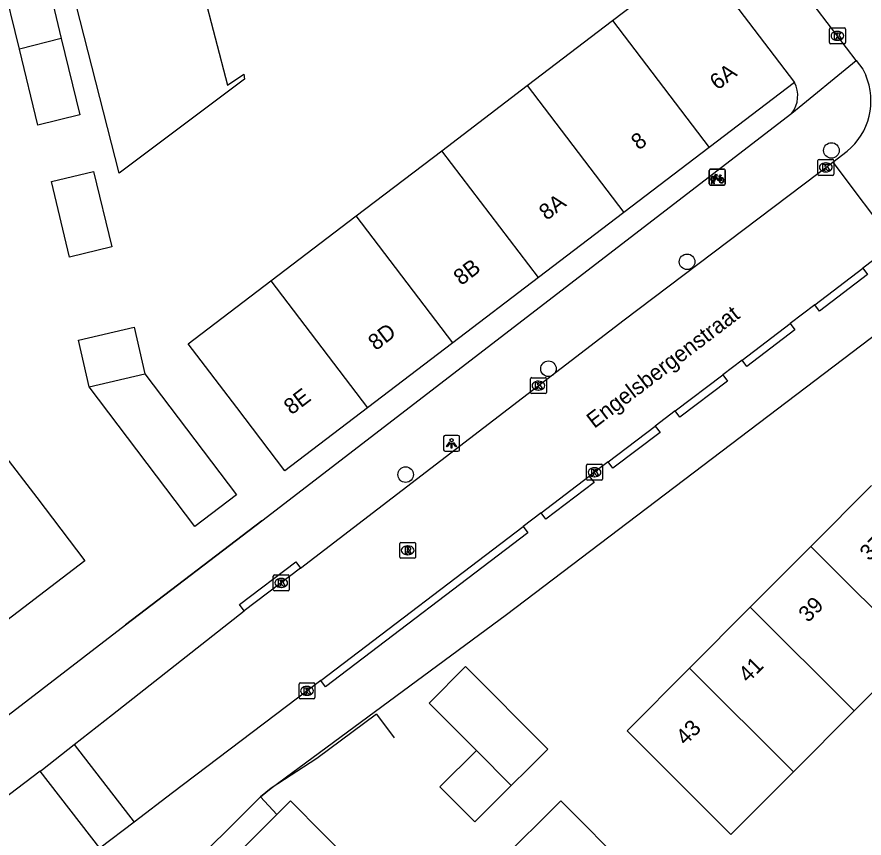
# Model space of a CAD drawing. Extents: x 159961 to 160856, y 382704 to 383353.
# Drawn here: x 160039 to 160092.3, y 383159 to 383210.6 of the extents above; entities that cross this region are included whole.
import ezdxf

# ---------------------------------------------------------------- set-up
doc = ezdxf.new("R2010")
doc.units = 0
for name, color, linetype in [('IMGEO_Boom', 7, 'Continuous'), ('IMGEO_Fietsenrek', 7, 'Continuous'), ('IMGEO_Kolk', 7, 'Continuous'), ('IMGEO_Lichtpunt', 7, 'Continuous'), ('IMGEO_Muur', 7, 'Continuous'), ('IMGEO_Openbare_ruimte_label', 7, 'Continuous'), ('IMGEO_Pand', 7, 'Continuous'), ('IMGEO_Pand_nummerreeks', 7, 'Continuous'), ('IMGEO_Rijbaan_lokaal_open', 7, 'Continuous'), ('IMGEO_Rioolput', 7, 'Continuous'), ('IMGEO_Voetpad_open', 7, 'Continuous')]:
    doc.layers.add(name, color=color, linetype=linetype)

msp = doc.modelspace()

# ---------------------------------------------------------------- linework, layer by layer
at = {"layer": 'IMGEO_Boom'}
for centre in [(160090.197, 383202.176), (160081.127, 383195.18), (160072.413, 383188.462), (160063.433, 383181.809)]:
    msp.add_circle(centre, 0.489, dxfattribs=at)
at = {"layer": 'IMGEO_Fietsenrek'}
for p, q in [((160082.523, 383200.074), (160082.523, 383200.915)), ((160082.523, 383200.915), (160082.523, 383200.074)), ((160082.598, 383200.999), (160083.439, 383200.999)), ((160083.439, 383200.999), (160082.598, 383200.999)), ((160083.523, 383200.924), (160083.523, 383200.083)), ((160083.523, 383200.083), (160083.523, 383200.924)), ((160082.65, 383200.083), (160082.689, 383200.243)), ((160082.719, 383200.231), (160082.684, 383200.083)), ((160082.761, 383200.255), (160082.76, 383200.259)), ((160082.802, 383200.083), (160082.768, 383200.225)), ((160082.792, 383200.266), (160082.793, 383200.259)), ((160082.8, 383200.229), (160082.835, 383200.083)), ((160083.21, 383200.548), (160083.246, 383200.453)), ((160083.448, 383199.999), (160082.607, 383199.999)), ((160082.607, 383199.999), (160083.448, 383199.999)), ((160082.684, 383200.083), (160082.65, 383200.083)), ((160082.835, 383200.083), (160082.802, 383200.083))]:
    msp.add_line(p, q, dxfattribs=at)
for points in [[(160082.836, 383200.525), (160082.931, 383200.689), (160083.017, 383200.675), (160083.019, 383200.666), (160082.963, 383200.655), (160082.936, 383200.61), (160083.192, 383200.569)], [(160082.857, 383200.473), (160082.805, 383200.383), (160082.765, 383200.358), (160082.766, 383200.405), (160082.821, 383200.499)], [(160083.132, 383200.281), (160083.082, 383200.281), (160082.891, 383200.532), (160082.872, 383200.5)], [(160083.179, 383200.544), (160082.922, 383200.585), (160082.905, 383200.556), (160083.072, 383200.336), (160083.179, 383200.544)], [(160083.227, 383200.446), (160083.197, 383200.523), (160083.088, 383200.305), (160083.131, 383200.305)], [(160083.161, 383200.305), (160083.281, 383200.304), (160083.237, 383200.418)], [(160083.257, 383200.425), (160083.312, 383200.28), (160083.162, 383200.28)], [(160083.192, 383200.569), (160083.217, 383200.618), (160083.211, 383200.622), (160083.188, 383200.626), (160083.176, 383200.633), (160083.175, 383200.636), (160083.177, 383200.641), (160083.272, 383200.626), (160083.274, 383200.616), (160083.264, 383200.603), (160083.252, 383200.597), (160083.238, 383200.603), (160083.21, 383200.548)]]:
    msp.add_lwpolyline(points, dxfattribs=at)
for centre, radius, start, end in [((160082.601, 383200.921), 0.0779, 92.4484, 184.2845), ((160082.601, 383200.921), 0.0779, 92.4484, 184.2845), ((160083.445, 383200.921), 0.0779, 2.4484, 94.2845), ((160083.445, 383200.921), 0.0779, 2.4484, 94.2845), ((160082.763, 383200.384), 0.159, 62.6766, 242.1369), ((160082.763, 383200.384), 0.129, 63.3192, 238.903), ((160082.743, 383200.255), 0.0499, 12.8025, 158.6934), ((160082.763, 383200.384), 0.159, 253.9967, 271.7867), ((160082.743, 383200.255), 0.0174, 12.8025, 163.4502), ((160082.763, 383200.384), 0.129, 253.415, 269.0204), ((160082.763, 383200.384), 0.129, 283.6043, 43.4302), ((160082.763, 383200.384), 0.159, 283.5766, 46.6042), ((160083.29, 383200.3), 0.159, 113.3408, 178.3217), ((160083.29, 383200.3), 0.159, 187.0065, 105.7708), ((160083.29, 383200.3), 0.129, 113.923, 177.9556), ((160083.29, 383200.3), 0.129, 188.6715, 104.5883), ((160082.601, 383200.077), 0.0779, 182.4484, 274.2845), ((160082.601, 383200.077), 0.0779, 182.4484, 274.2845), ((160083.445, 383200.077), 0.0779, 272.4484, 4.2845), ((160083.445, 383200.077), 0.0779, 272.4484, 4.2845)]:
    msp.add_arc(centre, radius, start, end, dxfattribs=at)
at = {"layer": 'IMGEO_Kolk'}
for p, q in [((160090.077, 383208.951), (160090.077, 383209.803)), ((160090.152, 383209.877), (160091.004, 383209.877)), ((160091.078, 383209.803), (160091.078, 383208.951)), ((160090.565, 383209.657), (160090.59, 383209.657)), ((160091.004, 383208.877), (160090.152, 383208.877)), ((160090.588, 383209.097), (160090.563, 383209.097)), ((160089.346, 383200.687), (160089.346, 383201.539)), ((160089.421, 383201.613), (160090.273, 383201.613)), ((160089.834, 383201.393), (160089.859, 383201.393)), ((160090.347, 383201.539), (160090.347, 383200.687)), ((160089.857, 383200.833), (160089.832, 383200.833)), ((160090.273, 383200.613), (160089.421, 383200.613)), ((160071.358, 383187.9), (160072.21, 383187.9)), ((160071.283, 383186.974), (160071.283, 383187.826)), ((160071.771, 383187.68), (160071.796, 383187.68)), ((160072.284, 383187.826), (160072.284, 383186.974)), ((160072.21, 383186.9), (160071.358, 383186.9)), ((160071.794, 383187.12), (160071.769, 383187.12)), ((160074.808, 383181.531), (160074.808, 383182.383)), ((160074.883, 383182.457), (160075.735, 383182.457)), ((160075.296, 383182.237), (160075.321, 383182.237)), ((160075.809, 383182.383), (160075.809, 383181.531)), ((160075.319, 383181.677), (160075.294, 383181.677)), ((160075.735, 383181.457), (160074.883, 383181.457)), ((160055.114, 383174.579), (160055.114, 383175.431)), ((160055.189, 383175.505), (160056.041, 383175.505)), ((160055.602, 383175.285), (160055.627, 383175.285)), ((160056.115, 383175.431), (160056.115, 383174.579)), ((160055.625, 383174.725), (160055.6, 383174.725)), ((160056.041, 383174.505), (160055.189, 383174.505)), ((160056.808, 383168.721), (160057.66, 383168.721)), ((160056.733, 383167.795), (160056.733, 383168.647)), ((160057.221, 383168.501), (160057.246, 383168.501)), ((160057.734, 383168.647), (160057.734, 383167.795)), ((160057.66, 383167.721), (160056.808, 383167.721)), ((160057.244, 383167.941), (160057.219, 383167.941))]:
    msp.add_line(p, q, dxfattribs=at)
for points in [[(160090.077, 383208.951), (160090.077, 383209.803)], [(160090.152, 383209.877), (160091.004, 383209.877)], [(160091.078, 383209.803), (160091.078, 383208.951)], [(160090.398, 383209.577), (160090.521, 383209.577), (160090.521, 383209.426), (160090.651, 383209.577), (160090.815, 383209.577), (160090.669, 383209.426), (160090.822, 383209.177), (160090.67, 383209.177), (160090.585, 383209.341), (160090.521, 383209.274), (160090.521, 383209.177), (160090.398, 383209.177), (160090.398, 383209.577)], [(160091.004, 383208.877), (160090.152, 383208.877)], [(160089.346, 383200.687), (160089.346, 383201.539)], [(160089.421, 383201.613), (160090.273, 383201.613)], [(160089.667, 383201.313), (160089.79, 383201.313), (160089.79, 383201.162), (160089.92, 383201.313), (160090.084, 383201.313), (160089.938, 383201.162), (160090.091, 383200.913), (160089.939, 383200.913), (160089.854, 383201.077), (160089.79, 383201.01), (160089.79, 383200.913), (160089.667, 383200.913), (160089.667, 383201.313)], [(160090.347, 383201.539), (160090.347, 383200.687)], [(160090.273, 383200.613), (160089.421, 383200.613)], [(160071.358, 383187.9), (160072.21, 383187.9)], [(160071.283, 383186.974), (160071.283, 383187.826)], [(160071.604, 383187.6), (160071.727, 383187.6), (160071.727, 383187.449), (160071.857, 383187.6), (160072.021, 383187.6), (160071.875, 383187.449), (160072.028, 383187.2), (160071.876, 383187.2), (160071.791, 383187.364), (160071.727, 383187.297), (160071.727, 383187.2), (160071.604, 383187.2), (160071.604, 383187.6)], [(160072.284, 383187.826), (160072.284, 383186.974)], [(160072.21, 383186.9), (160071.358, 383186.9)], [(160074.808, 383181.531), (160074.808, 383182.383)], [(160074.883, 383182.457), (160075.735, 383182.457)], [(160075.129, 383182.157), (160075.252, 383182.157), (160075.252, 383182.006), (160075.382, 383182.157), (160075.546, 383182.157), (160075.4, 383182.006), (160075.553, 383181.757), (160075.401, 383181.757), (160075.316, 383181.921), (160075.252, 383181.854), (160075.252, 383181.757), (160075.129, 383181.757), (160075.129, 383182.157)], [(160075.809, 383182.383), (160075.809, 383181.531)], [(160075.735, 383181.457), (160074.883, 383181.457)], [(160055.114, 383174.579), (160055.114, 383175.431)], [(160055.189, 383175.505), (160056.041, 383175.505)], [(160055.435, 383175.205), (160055.558, 383175.205), (160055.558, 383175.054), (160055.688, 383175.205), (160055.852, 383175.205), (160055.706, 383175.054), (160055.859, 383174.805), (160055.707, 383174.805), (160055.622, 383174.969), (160055.558, 383174.902), (160055.558, 383174.805), (160055.435, 383174.805), (160055.435, 383175.205)], [(160056.115, 383175.431), (160056.115, 383174.579)], [(160056.041, 383174.505), (160055.189, 383174.505)], [(160056.808, 383168.721), (160057.66, 383168.721)], [(160056.733, 383167.795), (160056.733, 383168.647)], [(160057.054, 383168.421), (160057.177, 383168.421), (160057.177, 383168.27), (160057.307, 383168.421), (160057.471, 383168.421), (160057.325, 383168.27), (160057.478, 383168.021), (160057.326, 383168.021), (160057.241, 383168.185), (160057.177, 383168.118), (160057.177, 383168.021), (160057.054, 383168.021), (160057.054, 383168.421)], [(160057.734, 383168.647), (160057.734, 383167.795)], [(160057.66, 383167.721), (160056.808, 383167.721)]]:
    msp.add_lwpolyline(points, dxfattribs=at)
for centre, start, end in [((160090.154, 383209.801), 91.552, 178.448), ((160090.154, 383209.801), 91.552, 178.448), ((160091.002, 383209.801), 1.552, 88.448), ((160091.002, 383209.801), 1.552, 88.448), ((160090.154, 383208.953), 181.552, 268.448), ((160090.154, 383208.953), 181.552, 268.448), ((160091.002, 383208.953), 271.552, 358.448), ((160091.002, 383208.953), 271.552, 358.448), ((160089.423, 383201.537), 91.552, 178.448), ((160089.423, 383201.537), 91.552, 178.448), ((160090.271, 383201.537), 1.552, 88.448), ((160090.271, 383201.537), 1.552, 88.448), ((160089.423, 383200.689), 181.552, 268.448), ((160089.423, 383200.689), 181.552, 268.448), ((160090.271, 383200.689), 271.552, 358.448), ((160090.271, 383200.689), 271.552, 358.448), ((160071.36, 383187.824), 91.552, 178.448), ((160071.36, 383187.824), 91.552, 178.448), ((160072.208, 383187.824), 1.552, 88.448), ((160072.208, 383187.824), 1.552, 88.448), ((160071.36, 383186.976), 181.552, 268.448), ((160071.36, 383186.976), 181.552, 268.448), ((160072.208, 383186.976), 271.552, 358.448), ((160072.208, 383186.976), 271.552, 358.448), ((160074.885, 383182.381), 91.552, 178.448), ((160074.885, 383182.381), 91.552, 178.448), ((160075.733, 383182.381), 1.552, 88.448), ((160075.733, 383182.381), 1.552, 88.448), ((160074.885, 383181.533), 181.552, 268.448), ((160074.885, 383181.533), 181.552, 268.448), ((160075.733, 383181.533), 271.552, 358.448), ((160075.733, 383181.533), 271.552, 358.448), ((160055.191, 383175.429), 91.552, 178.448), ((160055.191, 383175.429), 91.552, 178.448), ((160056.039, 383175.429), 1.552, 88.448), ((160056.039, 383175.429), 1.552, 88.448), ((160055.191, 383174.581), 181.552, 268.448), ((160055.191, 383174.581), 181.552, 268.448), ((160056.039, 383174.581), 271.552, 358.448), ((160056.039, 383174.581), 271.552, 358.448), ((160056.81, 383168.645), 91.552, 178.448), ((160056.81, 383168.645), 91.552, 178.448), ((160057.658, 383168.645), 1.552, 88.448), ((160057.658, 383168.645), 1.552, 88.448), ((160056.81, 383167.797), 181.552, 268.448), ((160056.81, 383167.797), 181.552, 268.448), ((160057.658, 383167.797), 271.552, 358.448), ((160057.658, 383167.797), 271.552, 358.448)]:
    msp.add_arc(centre, 0.0765, start, end, dxfattribs=at)
for centre, major_axis, ratio, start_param, end_param in [((160090.564, 383209.377), (-0.387, 0.002), 0.722429, 4.712389, 7.853982), ((160090.589, 383209.377), (-0.39, 0.002), 0.717154, 1.570796, 4.712389), ((160089.833, 383201.113), (-0.387, 0.002), 0.722429, 4.712389, 7.853982), ((160089.858, 383201.113), (-0.39, 0.002), 0.717154, 1.570796, 4.712389), ((160071.77, 383187.4), (-0.387, 0.002), 0.722429, 4.712389, 7.853982), ((160071.795, 383187.4), (-0.39, 0.002), 0.717154, 1.570796, 4.712389), ((160075.295, 383181.957), (-0.387, 0.002), 0.722429, 4.712389, 7.853982), ((160075.32, 383181.957), (-0.39, 0.002), 0.717154, 1.570796, 4.712389), ((160055.601, 383175.005), (-0.387, 0.002), 0.722429, 4.712389, 7.853982), ((160055.626, 383175.005), (-0.39, 0.002), 0.717154, 1.570796, 4.712389), ((160057.22, 383168.221), (-0.387, 0.002), 0.722429, 4.712389, 7.853982), ((160057.245, 383168.221), (-0.39, 0.002), 0.717154, 1.570796, 4.712389)]:
    msp.add_ellipse(centre, major_axis=major_axis, ratio=ratio, start_param=start_param, end_param=end_param, dxfattribs=at)
at = {"layer": 'IMGEO_Lichtpunt'}
for p, q in [((160065.821, 383184.173), (160065.821, 383183.366)), ((160065.821, 383184.173), (160065.821, 383183.366)), ((160066.723, 383184.268), (160065.915, 383184.268)), ((160066.723, 383184.268), (160065.915, 383184.268)), ((160066.817, 383183.366), (160066.817, 383184.173)), ((160066.817, 383183.366), (160066.817, 383184.173)), ((160065.915, 383183.272), (160066.723, 383183.272)), ((160065.915, 383183.272), (160066.723, 383183.272))]:
    msp.add_line(p, q, dxfattribs=at)
for points in [[(160066.195, 383183.837), (160066.234, 383183.809), (160066.046, 383183.547), (160066.008, 383183.574), (160066.195, 383183.837)], [(160066.297, 383183.789), (160066.344, 383183.789), (160066.344, 383183.467), (160066.297, 383183.467), (160066.297, 383183.789)], [(160066.407, 383183.809), (160066.445, 383183.836), (160066.632, 383183.574), (160066.593, 383183.546), (160066.407, 383183.809)]]:
    msp.add_lwpolyline(points, dxfattribs=at)
msp.add_circle((160066.32, 383183.971), 0.0994, dxfattribs=at)
for centre, start, end in [((160065.915, 383184.173), 90, 180), ((160065.915, 383184.173), 90, 180), ((160066.723, 383184.173), 0, 90), ((160066.723, 383184.173), 0, 90), ((160065.915, 383183.366), 180, 270), ((160065.915, 383183.366), 180, 270), ((160066.723, 383183.366), 270, 0), ((160066.723, 383183.366), 270, 360)]:
    msp.add_arc(centre, 0.0946, start, end, dxfattribs=at)
at = {"layer": 'IMGEO_Muur'}
for points in [[(160054.384, 383178.911), (160045.83, 383172.362)], [(160061.599, 383166.762), (160057.851, 383163.97), (160054.98, 383162.099)], [(160061.599, 383166.762), (160062.72, 383165.276)], [(160054.98, 383162.099), (160054.318, 383161.568)], [(160054.318, 383161.568), (160055.334, 383160.453)]]:
    msp.add_lwpolyline(points, dxfattribs=at)
at = {"layer": 'IMGEO_Pand'}
for points in [[(160050.551, 383243.936), (160057.259, 383217.273), (160053.285, 383214.239), (160050.679, 383212.249), (160052.23, 383206.273), (160053.268, 383206.976), (160053.31, 383206.652), (160045.418, 383200.751), (160033.158, 383248.653), (160046.039, 383250), (160049.499, 383250.372)], [(160076.439, 383210.345), (160077.814, 383211.392), (160081.83, 383214.404)], [(160081.83, 383214.404), (160087.886, 383206.456)], [(160039.15, 383208.547), (160038.055, 383213.083), (160040.7, 383213.722), (160041.788, 383209.216)], [(160071.07, 383206.254), (160076.439, 383210.345)], [(160076.439, 383210.345), (160082.517, 383202.366)], [(160041.788, 383209.216), (160042.949, 383204.406), (160040.304, 383203.768), (160039.15, 383208.547)], [(160041.788, 383209.216), (160039.15, 383208.547)], [(160065.7, 383202.163), (160071.07, 383206.254)], [(160071.07, 383206.254), (160077.148, 383198.275)], [(160087.886, 383206.456), (160082.517, 383202.366)], [(160082.517, 383202.366), (160077.148, 383198.275)], [(160060.331, 383198.073), (160065.7, 383202.163)], [(160071.778, 383194.184), (160065.7, 383202.163)], [(160044.965, 383196.123), (160042.295, 383195.467), (160041.171, 383200.236), (160043.802, 383200.857), (160044.965, 383196.123)], [(160054.962, 383193.982), (160060.331, 383198.073)], [(160066.41, 383190.094), (160060.331, 383198.073)], [(160077.148, 383198.275), (160071.778, 383194.184)], [(160061.04, 383186.003), (160055.844, 383182.044), (160052.814, 383186.022), (160049.765, 383190.023), (160054.962, 383193.982)], [(160054.962, 383193.982), (160061.04, 383186.003)], [(160071.778, 383194.184), (160066.41, 383190.094)], [(160043.538, 383187.331), (160042.865, 383190.264), (160046.359, 383191.066), (160047.032, 383188.132)], [(160066.41, 383190.094), (160061.04, 383186.003)], [(160047.032, 383188.132), (160052.795, 383180.528), (160050.19, 383178.554), (160043.538, 383187.331)], [(160043.538, 383187.331), (160047.032, 383188.132)], [(160038.09, 383183.182), (160040.239, 383180.368), (160043.269, 383176.39), (160036.909, 383171.544), (160037.253, 383171.093), (160034.707, 383169.154), (160031.447, 383173.434), (160032.066, 383173.905), (160029.54, 383177.22)], [(160088.914, 383177.3), (160092.728, 383181.123)], [(160085.1, 383173.478), (160088.914, 383177.3)], [(160088.914, 383177.3), (160095.439, 383170.785)], [(160081.286, 383169.656), (160085.1, 383173.478)], [(160091.626, 383166.962), (160085.1, 383173.478)], [(160095.439, 383170.785), (160091.626, 383166.962)], [(160067.886, 383164.471), (160064.912, 383167.457), (160067.206, 383169.741), (160072.367, 383164.557), (160071.126, 383163.321), (160070.073, 383162.274)], [(160087.812, 383163.14), (160087.418, 383162.745), (160083.886, 383159.205), (160077.358, 383165.718), (160081.286, 383169.656)], [(160081.286, 383169.656), (160087.812, 383163.14)], [(160091.626, 383166.962), (160087.812, 383163.14)], [(160070.073, 383162.274), (160067.779, 383159.99), (160065.592, 383162.187), (160067.886, 383164.471)], [(160070.073, 383162.274), (160067.886, 383164.471)], [(160052.491, 383149.02), (160048.19, 383153.34), (160055.334, 383160.453), (160056.188, 383161.303), (160058.261, 383159.221), (160060.513, 383156.97), (160058.428, 383154.924)], [(160073.613, 383153.046), (160069.263, 383157.415), (160073.183, 383161.316), (160077.534, 383156.945)]]:
    msp.add_lwpolyline(points, dxfattribs=at)
at = {"layer": 'IMGEO_Rijbaan_lokaal_open'}
for points in [[(160091.764, 383207.823), (160083.846, 383218.205)], [(160091.764, 383207.823), (160092.171, 383207.29), (160092.357, 383206.908)], [(160090.278, 383201.437), (160091.192, 383202.128)], [(160056.83, 383175.938), (160077.175, 383191.53), (160090.278, 383201.437)], [(160090.278, 383201.437), (160094.167, 383196.29)], [(160094.167, 383196.29), (160092.168, 383194.771)], [(160089.146, 383192.474), (160092.168, 383194.771)], [(160089.146, 383192.474), (160087.597, 383191.297)], [(160084.588, 383189.01), (160087.597, 383191.297)], [(160084.588, 383189.01), (160083.371, 383188.085)], [(160080.372, 383185.807), (160083.371, 383188.085)], [(160080.372, 383185.807), (160079.123, 383184.857)], [(160076.156, 383182.602), (160079.123, 383184.857)], [(160076.156, 383182.602), (160074.978, 383181.707)], [(160071.946, 383179.403), (160074.978, 383181.707)], [(160071.946, 383179.403), (160070.82, 383178.547)], [(160058.098, 383168.879), (160070.82, 383178.547)], [(160056.83, 383175.938), (160055.523, 383174.936), (160053.285, 383173.241)], [(160042.599, 383164.849), (160045.014, 383166.745), (160053.285, 383173.241)], [(160058.098, 383168.879), (160048.77, 383161.803), (160046.358, 383159.974)], [(160040.459, 383163.171), (160040.597, 383163.276), (160042.599, 383164.849)], [(160042.599, 383164.849), (160046.358, 383159.974)], [(160040.459, 383163.171), (160034.222, 383158.444)], [(160044.201, 383158.337), (160040.459, 383163.171)], [(160046.358, 383159.974), (160044.201, 383158.337)]]:
    msp.add_lwpolyline(points, dxfattribs=at)
msp.add_arc((160088.571, 383205.299), 4.113, 309.5734, 23.032, dxfattribs=at)
at = {"layer": 'IMGEO_Rioolput'}
for p, q in [((160063.062, 383176.624), (160063.062, 383177.476)), ((160063.137, 383177.55), (160063.989, 383177.55)), ((160063.55, 383177.33), (160063.575, 383177.33)), ((160064.063, 383177.476), (160064.063, 383176.624)), ((160063.573, 383176.77), (160063.548, 383176.77)), ((160063.989, 383176.55), (160063.137, 383176.55))]:
    msp.add_line(p, q, dxfattribs=at)
for points in [[(160063.062, 383176.624), (160063.062, 383177.476)], [(160063.137, 383177.55), (160063.989, 383177.55)], [(160063.651, 383177.248), (160063.399, 383177.25), (160063.399, 383176.85)], [(160064.063, 383177.476), (160064.063, 383176.624)], [(160063.399, 383176.85), (160063.523, 383176.85), (160063.523, 383177.012), (160063.534, 383177.012)], [(160063.577, 383177.169), (160063.523, 383177.169), (160063.523, 383177.088)], [(160063.523, 383177.088), (160063.575, 383177.088)], [(160063.581, 383176.983), (160063.652, 383176.85), (160063.792, 383176.85), (160063.727, 383176.976)], [(160063.989, 383176.55), (160063.137, 383176.55)]]:
    msp.add_lwpolyline(points, dxfattribs=at)
for centre, radius, start, end in [((160063.139, 383177.474), 0.0765, 91.552, 178.448), ((160063.139, 383177.474), 0.0765, 91.552, 178.448), ((160063.65, 383177.138), 0.109, 350.3612, 89.416), ((160063.987, 383177.474), 0.0765, 1.552, 88.448), ((160063.987, 383177.474), 0.0765, 1.552, 88.448), ((160063.533, 383176.959), 0.0533, 26.0293, 88.6989), ((160063.559, 383177.277), 0.19, 274.7715, 282.9687), ((160063.583, 383177.073), 0.0964, 77.0061, 93.1865), ((160063.597, 383177.13), 0.0378, 276.6634, 79.6772), ((160063.648, 383177.138), 0.112, 277.5842, 350.9817), ((160063.632, 383176.923), 0.108, 29.5134, 73.7905), ((160063.139, 383176.626), 0.0765, 181.552, 268.448), ((160063.139, 383176.626), 0.0765, 181.552, 268.448), ((160063.987, 383176.626), 0.0765, 271.552, 358.448), ((160063.987, 383176.626), 0.0765, 271.552, 358.448)]:
    msp.add_arc(centre, radius, start, end, dxfattribs=at)
for centre, major_axis, ratio, start_param, end_param in [((160063.549, 383177.05), (-0.387, 0.002), 0.722429, 4.712389, 7.853982), ((160063.574, 383177.05), (-0.39, 0.002), 0.717154, 1.570796, 4.712389)]:
    msp.add_ellipse(centre, major_axis=major_axis, ratio=ratio, start_param=start_param, end_param=end_param, dxfattribs=at)
at = {"layer": 'IMGEO_Voetpad_open'}
for points in [[(160043.886, 383151.186), (160054.318, 383161.568), (160054.98, 383162.099), (160069.776, 383173.027), (160139.659, 383226.049), (160145.341, 383230.36)], [(160087.717, 383204.52), (160091.764, 383207.823)], [(160030.576, 383162.332), (160031.679, 383161.996), (160032.597, 383162.207), (160045.83, 383172.362), (160054.384, 383178.911), (160087.717, 383204.52)], [(160092.168, 383194.771), (160092.47, 383194.373), (160089.448, 383192.076), (160089.146, 383192.474)], [(160087.597, 383191.297), (160087.899, 383190.899), (160084.89, 383188.612), (160084.588, 383189.01)], [(160083.371, 383188.085), (160083.673, 383187.687), (160080.674, 383185.409), (160080.372, 383185.807)], [(160079.123, 383184.857), (160079.426, 383184.46), (160076.459, 383182.205), (160076.156, 383182.602)], [(160074.978, 383181.707), (160075.281, 383181.31), (160072.249, 383179.006), (160071.946, 383179.403)], [(160070.82, 383178.547), (160071.122, 383178.149), (160058.4, 383168.481), (160058.098, 383168.879)], [(160053.285, 383173.241), (160052.983, 383173.639), (160056.528, 383176.336), (160056.83, 383175.938)]]:
    msp.add_lwpolyline(points, dxfattribs=at)
msp.add_arc((160086.232, 383205.625), 1.851, 323.3468, 26.6754, dxfattribs=at)

# ---------------------------------------------------------------- texts
at = {"layer": 'IMGEO_Openbare_ruimte_label'}
msp.add_text('Engelsbergenstraat', height=1, rotation=37.2823, dxfattribs=at).set_placement((160075.293, 383184.675))
at = {"layer": 'IMGEO_Pand_nummerreeks'}
for s, rotation, p in [('6A', 37.2994, (160083.035, 383205.929)), ('8', 37.3062, (160078.09, 383202.16)), ('8A', 37.3011, (160072.297, 383197.746)), ('8B', 37.3046, (160066.927, 383193.656)), ('8D', 37.3011, (160061.559, 383189.565)), ('8E', 37.3049, (160056.257, 383185.527)), ('37', 45.0656, (160092.582, 383176.332)), ('39', 45.0656, (160088.729, 383172.47)), ('41', 45.0656, (160084.956, 383168.688)), ('43', 45.0656, (160081.023, 383164.747))]:
    msp.add_text(s, height=1, rotation=rotation, dxfattribs=at).set_placement(p)

doc.saveas('drawing.dxf')
